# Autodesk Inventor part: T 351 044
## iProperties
Company: Mayer & Müller AG Schaltgeräte
Created: 2006-10
Part Number: T 351 044
Material: Ag-Ni90/10
Document SubType Name: Modeling
Designer: I.Baliuc
Manufacturer: Standard
Standards Organization: Custom
Description: Edelmetalplatte
Density: 10.49 g/cm^3
Zweck: für Hauptkontakt 340056
Author: T.Messerschmitt
Revision Number: 351044
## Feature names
1. Extrusion2
